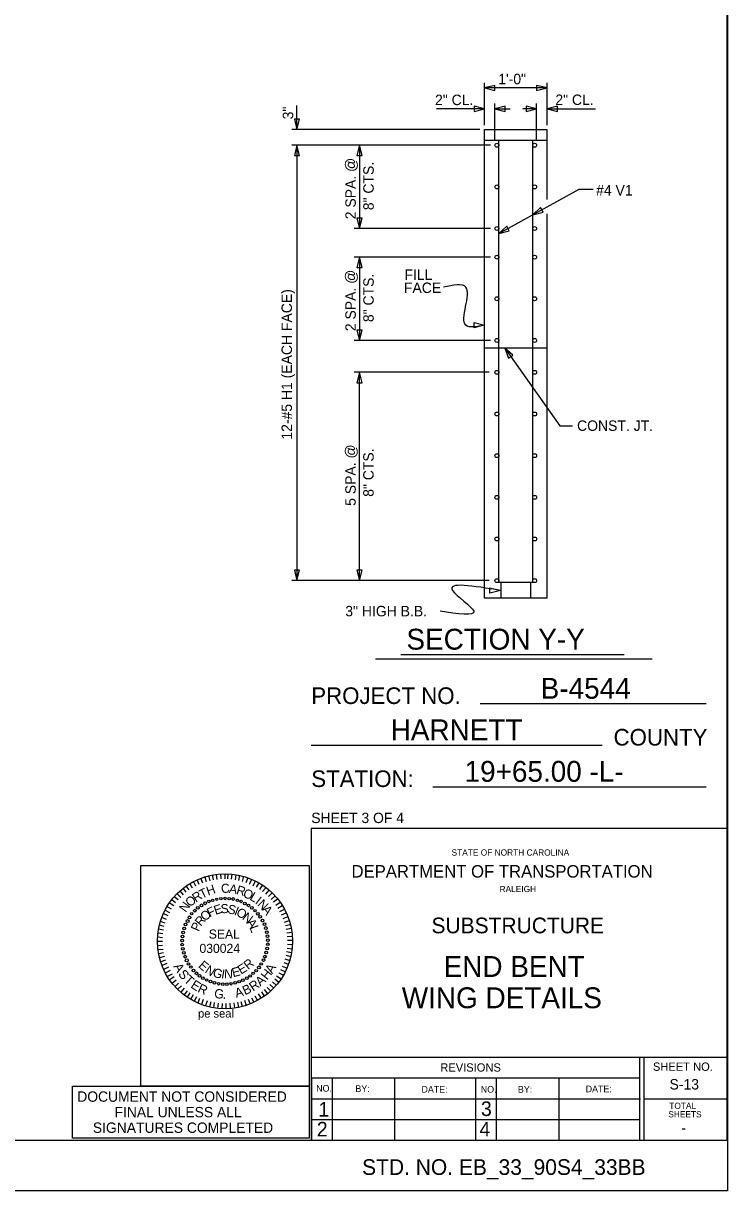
# Model space of a CAD drawing. Extents: x -41 to 251, y -169 to 237.
# Drawn here: x 32.71 to 43.97, y -98.91 to -80.23 of the extents above; entities that cross this region are included whole.
import ezdxf

# ---------------------------------------------------------------- set-up
doc = ezdxf.new("R2010")
doc.units = 0
for name, color, linetype in [('Arrowhead Terminators CELL', 7, 'Continuous'), ('Dimension Lines', 7, 'Continuous'), ('Mis Object Lines', 7, 'Continuous'), ('Mis Object Lines Hidden', 7, 'Continuous'), ('Peseal', 7, 'Continuous'), ('Plan Sheet CELL', 7, 'Continuous'), ('Plot Shape CELL', 7, 'Continuous'), ('Rebar Lines', 7, 'Continuous'), ('Sheet Sticker Exception Certification CELL', 7, 'Continuous'), ('Subtitle Text', 7, 'Continuous'), ('Text', 7, 'Continuous'), ('Title Text', 7, 'Continuous'), ('User Information Notes', 7, 'Continuous'), ('User Information Notes CELL', 7, 'Continuous')]:
    doc.layers.add(name, color=color, linetype=linetype)

msp = doc.modelspace()

# ---------------------------------------------------------------- linework, layer by layer
at = {"layer": 'Arrowhead Terminators CELL'}
for points in [[(40.084, -81.261), (40.25, -81.303), (40.25, -81.22)], [(41.084, -81.261), (40.918, -81.22), (40.918, -81.303)], [(40.084, -81.596), (39.918, -81.554), (39.918, -81.638)], [(40.251, -81.596), (40.417, -81.638), (40.417, -81.554)], [(40.918, -81.595), (40.751, -81.553), (40.751, -81.636)], [(41.084, -81.595), (41.25, -81.636), (41.25, -81.553)], [(37.084, -81.928), (37.126, -81.762), (37.043, -81.762)], [(37.084, -82.178), (37.043, -82.344), (37.126, -82.344)], [(38.084, -82.178), (38.043, -82.344), (38.126, -82.344)], [(40.855, -83.293), (41.021, -83.249), (40.981, -83.176)], [(38.084, -83.511), (38.126, -83.345), (38.043, -83.345)], [(40.314, -83.591), (40.479, -83.547), (40.439, -83.474)], [(38.084, -83.97), (38.043, -84.136), (38.126, -84.136)], [(38.084, -85.303), (38.126, -85.137), (38.043, -85.137)], [(40.084, -85.06), (39.918, -85.101), (39.918, -85.018)], [(40.408, -85.428), (40.47, -85.588), (40.538, -85.539)], [(38.084, -85.813), (38.043, -85.979), (38.126, -85.979)], [(37.084, -89.147), (37.126, -88.98), (37.043, -88.98)], [(38.084, -89.147), (38.126, -88.98), (38.043, -88.98)], [(40.338, -89.304), (40.172, -89.346), (40.172, -89.263)]]:
    msp.add_lwpolyline(points, close=True, dxfattribs=at)
at = {"layer": 'Dimension Lines'}
for p, q in [((40.084, -81.856), (40.084, -81.178)), ((41.084, -81.261), (40.084, -81.261)), ((41.084, -81.856), (41.084, -81.178)), ((37.084, -81.928), (37.084, -81.541)), ((40.084, -81.596), (39.314, -81.596)), ((40.251, -82.106), (40.251, -81.513)), ((40.251, -81.596), (40.497, -81.596)), ((40.918, -81.595), (40.695, -81.595)), ((40.918, -82.106), (40.918, -81.511)), ((41.084, -81.595), (41.859, -81.595)), ((40.012, -81.928), (37.001, -81.928)), ((40.18, -82.178), (37.001, -82.178)), ((37.084, -82.178), (37.084, -89.147)), ((38.084, -82.178), (38.084, -83.511)), ((40.314, -83.591), (41.598, -82.884)), ((41.598, -82.884), (41.824, -82.884)), ((40.18, -83.511), (38.001, -83.511)), ((40.18, -83.97), (38.001, -83.97)), ((38.084, -83.97), (38.084, -85.303)), ((40.18, -85.303), (38.001, -85.303)), ((40.408, -85.428), (41.29, -86.668)), ((40.16, -85.813), (38.001, -85.813)), ((38.084, -89.147), (38.084, -85.813)), ((41.29, -86.668), (41.494, -86.668)), ((40.16, -89.147), (37.001, -89.147))]:
    msp.add_line(p, q, dxfattribs=at)
for points in [[(40.084, -85.06), (39.787, -85.06), (39.787, -84.45), (39.429, -84.45)], [(40.338, -89.304), (39.572, -89.304), (39.911, -89.636), (39.374, -89.636)]]:
    msp.add_spline(points, degree=3, dxfattribs=at)
at = {"layer": 'Mis Object Lines'}
for p, q in [((40.084, -89.428), (40.084, -81.928)), ((40.084, -81.928), (41.084, -81.928)), ((41.084, -83.049), (41.084, -81.928)), ((41.084, -89.428), (41.084, -83.275)), ((41.084, -89.428), (40.084, -89.428))]:
    msp.add_line(p, q, dxfattribs=at)
at = {"layer": 'Mis Object Lines Hidden'}
msp.add_line((41.084, -85.428), (40.084, -85.428), dxfattribs=at)
at = {"layer": 'Peseal'}
for p, q in [((35.465, -94.035), (35.429, -93.962)), ((35.517, -94.009), (35.486, -93.936)), ((35.579, -93.988), (35.548, -93.91)), ((35.637, -93.967), (35.611, -93.884)), ((35.694, -93.952), (35.673, -93.868)), ((35.751, -93.936), (35.735, -93.853)), ((35.808, -93.931), (35.798, -93.848)), ((35.87, -93.92), (35.865, -93.837)), ((35.933, -93.92), (35.933, -93.837)), ((35.979, -93.92), (35.985, -93.837)), ((36.037, -93.926), (36.047, -93.842)), ((36.099, -93.936), (36.109, -93.853)), ((36.156, -93.946), (36.172, -93.863)), ((36.213, -93.962), (36.234, -93.879)), ((36.27, -93.977), (36.302, -93.9)), ((36.327, -94.003), (36.364, -93.926)), ((36.385, -94.029), (36.421, -93.952)), ((35.226, -94.216), (35.164, -94.154)), ((35.268, -94.175), (35.216, -94.113)), ((35.314, -94.133), (35.262, -94.071)), ((35.361, -94.097), (35.314, -94.029)), ((35.413, -94.066), (35.372, -93.993)), ((36.437, -94.055), (36.478, -93.983)), ((36.489, -94.092), (36.535, -94.019)), ((36.535, -94.123), (36.587, -94.061)), ((36.587, -94.165), (36.639, -94.102)), ((36.629, -94.201), (36.686, -94.144)), ((35.112, -94.352), (35.039, -94.305)), ((35.143, -94.305), (35.081, -94.258)), ((35.185, -94.258), (35.122, -94.206)), ((36.67, -94.248), (36.733, -94.19)), ((36.707, -94.289), (36.774, -94.237)), ((36.748, -94.341), (36.816, -94.294)), ((35.023, -94.513), (34.946, -94.476)), ((35.049, -94.461), (34.972, -94.419)), ((35.075, -94.404), (35.003, -94.362)), ((36.779, -94.388), (36.847, -94.346)), ((36.811, -94.44), (36.883, -94.404)), ((36.837, -94.497), (36.909, -94.461)), ((36.863, -94.554), (36.941, -94.523)), ((34.961, -94.684), (34.883, -94.663)), ((34.977, -94.627), (34.899, -94.601)), ((34.997, -94.57), (34.92, -94.539)), ((36.883, -94.611), (36.961, -94.585)), ((36.899, -94.668), (36.977, -94.648)), ((36.909, -94.726), (36.992, -94.71)), ((34.935, -94.861), (34.852, -94.855)), ((34.94, -94.798), (34.862, -94.788)), ((34.951, -94.741), (34.868, -94.726)), ((36.92, -94.783), (37.003, -94.772)), ((36.925, -94.84), (37.008, -94.835)), ((36.93, -94.902), (37.013, -94.902)), ((34.935, -94.923), (34.852, -94.923)), ((34.935, -94.985), (34.852, -94.991)), ((34.946, -95.048), (34.862, -95.058)), ((36.915, -95.084), (36.998, -95.1)), ((36.925, -95.027), (37.008, -95.037)), ((36.93, -94.965), (37.013, -94.97)), ((34.951, -95.105), (34.873, -95.12)), ((34.966, -95.162), (34.883, -95.183)), ((34.982, -95.219), (34.904, -95.245)), ((35.003, -95.276), (34.925, -95.307)), ((36.873, -95.256), (36.951, -95.287)), ((36.889, -95.198), (36.972, -95.224)), ((36.904, -95.141), (36.987, -95.162)), ((35.029, -95.333), (34.951, -95.37)), ((35.055, -95.385), (34.977, -95.427)), ((35.086, -95.443), (35.013, -95.484)), ((36.795, -95.422), (36.868, -95.463)), ((36.821, -95.37), (36.899, -95.406)), ((36.847, -95.318), (36.925, -95.349)), ((35.117, -95.489), (35.049, -95.536)), ((35.153, -95.541), (35.086, -95.593)), ((35.19, -95.588), (35.133, -95.64)), ((35.236, -95.63), (35.174, -95.692)), ((36.65, -95.609), (36.712, -95.671)), ((36.691, -95.567), (36.754, -95.624)), ((36.728, -95.521), (36.795, -95.572)), ((36.759, -95.474), (36.831, -95.521)), ((35.278, -95.671), (35.226, -95.734)), ((35.325, -95.713), (35.278, -95.775)), ((35.372, -95.744), (35.325, -95.811)), ((35.424, -95.775), (35.382, -95.848)), ((35.475, -95.806), (35.439, -95.879)), ((35.527, -95.832), (35.496, -95.905)), ((36.359, -95.822), (36.395, -95.895)), ((36.411, -95.791), (36.452, -95.869)), ((36.463, -95.759), (36.509, -95.832)), ((36.515, -95.728), (36.561, -95.796)), ((36.561, -95.692), (36.613, -95.759)), ((36.608, -95.656), (36.66, -95.713)), ((35.585, -95.853), (35.559, -95.931)), ((35.647, -95.874), (35.621, -95.952)), ((35.704, -95.889), (35.683, -95.967)), ((35.761, -95.9), (35.746, -95.983)), ((35.824, -95.91), (35.813, -95.993)), ((35.886, -95.915), (35.881, -95.998)), ((35.948, -95.915), (35.948, -95.998)), ((36.011, -95.91), (36.016, -95.993)), ((36.073, -95.905), (36.083, -95.988)), ((36.13, -95.895), (36.146, -95.978)), ((36.187, -95.884), (36.208, -95.962)), ((36.244, -95.863), (36.27, -95.947)), ((36.302, -95.843), (36.333, -95.921))]:
    msp.add_line(p, q, dxfattribs=at)
for centre, radius in [((35.556, -94.344), 0.0223), ((35.616, -94.31), 0.0232), ((35.675, -94.281), 0.0198), ((35.735, -94.261), 0.0189), ((35.8, -94.245), 0.0184), ((35.868, -94.237), 0.0209), ((35.933, -94.232), 0.0208), ((35.998, -94.237), 0.0209), ((36.063, -94.242), 0.0214), ((36.13, -94.261), 0.0189), ((36.19, -94.281), 0.0198), ((36.25, -94.313), 0.0209), ((36.307, -94.344), 0.0209), ((35.364, -94.536), 0.0223), ((35.4, -94.479), 0.0184), ((35.449, -94.429), 0.022), ((35.499, -94.385), 0.0223), ((36.361, -94.383), 0.0203), ((36.413, -94.429), 0.0203), ((36.457, -94.479), 0.0203), ((36.496, -94.528), 0.0209), ((35.278, -94.713), 0.0222), ((35.301, -94.65), 0.0198), ((35.333, -94.596), 0.0239), ((36.533, -94.585), 0.0209), ((36.564, -94.645), 0.0198), ((36.587, -94.707), 0.0222), ((35.247, -94.907), 0.0208), ((35.252, -94.843), 0.0209), ((35.262, -94.778), 0.0214), ((36.603, -94.772), 0.0214), ((36.613, -94.837), 0.0209), ((36.618, -94.902), 0.0208), ((35.247, -94.972), 0.0209), ((35.257, -95.04), 0.0209), ((35.273, -95.105), 0.0214), ((36.592, -95.1), 0.0214), ((36.608, -95.035), 0.0209), ((36.618, -94.967), 0.0209), ((35.294, -95.165), 0.0222), ((35.32, -95.224), 0.0232), ((35.348, -95.282), 0.0209), ((36.512, -95.282), 0.0209), ((36.548, -95.219), 0.0209), ((36.572, -95.165), 0.0222), ((35.387, -95.331), 0.0203), ((35.429, -95.385), 0.022), ((35.475, -95.432), 0.022), ((35.525, -95.471), 0.0223), ((36.335, -95.474), 0.0203), ((36.382, -95.432), 0.0203), ((36.431, -95.388), 0.0203), ((36.476, -95.336), 0.0223), ((35.579, -95.508), 0.0209), ((35.639, -95.539), 0.0198), ((35.701, -95.562), 0.0222), ((35.766, -95.583), 0.0214), ((35.831, -95.598), 0.0209), ((35.896, -95.604), 0.0208), ((35.964, -95.604), 0.0208), ((36.029, -95.598), 0.0209), ((36.094, -95.583), 0.0214), ((36.159, -95.565), 0.0198), ((36.218, -95.541), 0.0232), ((36.281, -95.508), 0.0209)]:
    msp.add_circle(centre, radius, dxfattribs=at)
at = {"layer": 'Plan Sheet CELL'}
for p, q in [((43.962, -70.174), (43.962, -98.104)), ((43.63, -91.121), (40.016, -91.121)), ((41.967, -91.786), (37.313, -91.786)), ((43.63, -92.45), (39.255, -92.45)), ((43.962, -93.116), (37.313, -93.116)), ((37.313, -93.116), (37.313, -98.104)), ((37.313, -96.773), (43.962, -96.773)), ((42.566, -96.773), (42.566, -98.104)), ((42.633, -96.773), (42.633, -98.104)), ((37.313, -97.105), (42.569, -97.105)), ((37.317, -97.105), (37.317, -98.104)), ((37.645, -97.105), (37.645, -98.104)), ((38.642, -97.111), (38.642, -98.109)), ((39.94, -97.105), (39.94, -98.112)), ((40.273, -97.105), (40.273, -98.104)), ((41.271, -97.105), (41.271, -98.104)), ((37.313, -97.438), (42.58, -97.438)), ((42.633, -97.438), (43.951, -97.438)), ((37.313, -97.771), (42.569, -97.771)), ((1.402, -98.104), (43.962, -98.104)), ((43.974, -98.91), (43.974, -98.91))]:
    msp.add_line(p, q, dxfattribs=at)
at = {"layer": 'Plot Shape CELL'}
msp.add_lwpolyline([(0, -69.65), (43.974, -69.65), (43.974, -98.91), (0, -98.91)], close=True, dxfattribs=at)
at = {"layer": 'Rebar Lines'}
for p, q in [((40.314, -89.178), (40.314, -82.095)), ((40.855, -89.178), (40.855, -82.095)), ((40.886, -89.178), (40.282, -89.178)), ((40.346, -89.178), (40.346, -89.428)), ((40.821, -89.178), (40.821, -89.428))]:
    msp.add_line(p, q, dxfattribs=at)
for centre in [(40.282, -82.178), (40.886, -82.178), (40.282, -82.845), (40.886, -82.845), (40.282, -83.511), (40.886, -83.511), (40.282, -83.97), (40.886, -83.97), (40.282, -84.636), (40.886, -84.636), (40.282, -85.303), (40.886, -85.303), (40.282, -85.813), (40.886, -85.813), (40.282, -86.48), (40.886, -86.48), (40.282, -87.147), (40.886, -87.147), (40.282, -87.813), (40.886, -87.813), (40.282, -88.48), (40.886, -88.48), (40.282, -89.147), (40.886, -89.147)]:
    msp.add_ellipse(centre, major_axis=(0, -0.0313), ratio=0.99999, dxfattribs=at)
at = {"layer": 'Sheet Sticker Exception Certification CELL'}
msp.add_lwpolyline([(33.491, -97.237), (37.279, -97.237), (37.279, -98.07), (33.491, -98.07)], close=True, dxfattribs=at)
at = {"layer": 'Title Text'}
for p, q in [((38.342, -90.4), (42.764, -90.4)), ((38.745, -90.327), (42.319, -90.327))]:
    msp.add_line(p, q, dxfattribs=at)
at = {"layer": 'User Information Notes'}
msp.add_line((35.933, -94.918), (35.933, -94.918), dxfattribs=at)
at = {"layer": 'User Information Notes CELL'}
for p, q in [((40.084, -82.095), (41.084, -82.095)), ((35.933, -94.918), (35.933, -94.918))]:
    msp.add_line(p, q, dxfattribs=at)
msp.add_lwpolyline([(34.586, -93.704), (37.279, -93.704), (37.279, -97.237), (34.586, -97.237)], close=True, dxfattribs=at)
msp.add_circle((35.933, -94.918), 1.081, dxfattribs=at)

# ---------------------------------------------------------------- texts
at = {"layer": 'Peseal'}
for s, height, rotation, p in [('R', 0.145, 32.9699, (35.465, -94.3)), ('T', 0.145, 25.943, (35.564, -94.242)), ('H', 0.145, 18.9162, (35.662, -94.19)), ('C', 0.145, 4.8625, (35.875, -94.149)), ('A', 0.145, 350.8088, (35.99, -94.144)), ('R', 0.145, 343.7819, (36.104, -94.159)), ('O', 0.145, 336.7551, (36.208, -94.201)), ('L', 0.145, 329.7282, (36.317, -94.248)), ('N', 0.145, 54.0504, (35.304, -94.466)), ('O', 0.145, 39.9967, (35.372, -94.378)), ('E', 0.145, 18.4448, (35.782, -94.497)), ('S', 0.145, 2.3789, (35.865, -94.471)), ('S', 0.145, 346.313, (35.964, -94.466)), ('I', 0.145, 322.7014, (36.405, -94.305)), ('N', 0.145, 315.6745, (36.442, -94.336)), ('R', 0.145, 50.5765, (35.548, -94.689)), ('O', 0.145, 42.5436, (35.616, -94.606)), ('F', 0.145, 26.4777, (35.688, -94.539)), ('I', 0.145, 338.28, (36.068, -94.492)), ('O', 0.145, 330.2471, (36.099, -94.497)), ('N', 0.145, 322.2141, (36.198, -94.559)), ('A', 0.145, 308.6477, (36.515, -94.414)), ('P', 0.145, 66.6424, (35.512, -94.772)), ('A', 0.145, 306.1483, (36.27, -94.622)), ('L', 0.145, 290.0824, (36.322, -94.694)), ('E', 0.145, 318.5179, (35.496, -95.323)), ('E', 0.145, 30.6815, (36.187, -95.453)), ('R', 0.145, 38.6997, (36.302, -95.38)), ('A', 0.148, 300.3993, (35.102, -95.321)), ('S', 0.148, 309.4349, (35.175, -95.447)), ('T', 0.148, 318.1096, (35.264, -95.555)), ('N', 0.145, 326.5361, (35.6, -95.411)), ('G', 0.145, 342.5725, (35.725, -95.479)), ('I', 0.145, 350.5906, (35.865, -95.51)), ('N', 0.145, 358.6088, (35.917, -95.51)), ('E', 0.145, 14.6452, (36.063, -95.495)), ('H', 0.148, 51.3597, (36.606, -95.549)), ('A', 0.148, 59.6007, (36.69, -95.446)), ('E', 0.148, 327.1453, (35.372, -95.652)), ('R', 0.148, 335.458, (35.484, -95.725)), ('B', 0.148, 24.8312, (36.253, -95.784)), ('R', 0.148, 33.5776, (36.381, -95.725)), ('A', 0.148, 42.3241, (36.499, -95.647)), ('G', 0.148, 353.3858, (35.754, -95.824)), ('.', 0.148, 2.1323, (35.894, -95.841)), ('A', 0.148, 15.7955, (36.113, -95.824))]:
    msp.add_text(s, height=height, rotation=rotation, dxfattribs=at).set_placement(p)
for s, p in [('SEAL', (35.673, -94.876)), ('030024', (35.524, -95.105))]:
    msp.add_text(s, height=0.1455, dxfattribs=at).set_placement(p)
at = {"layer": 'Plan Sheet CELL'}
for s, height, p in [('PROJECT NO.', 0.266, (37.313, -91.121)), ('COUNTY', 0.266, (42.149, -91.786)), ('STATION:', 0.266, (37.313, -92.45)), ('SHEET 3 OF 4', 0.16625, (37.313, -93.027)), ('STATE OF NORTH CAROLINA', 0.09974, (39.557, -93.548)), ('DEPARTMENT OF TRANSPORTATION', 0.19949, (37.957, -93.899)), ('RALEIGH', 0.0997, (40.325, -94.132)), ('REVISIONS', 0.133, (39.377, -97.005)), ('SHEET NO.', 0.133, (42.779, -96.992)), ('NO.', 0.106, (37.391, -97.325)), ('BY:', 0.106, (38.019, -97.33)), ('DATE:', 0.106, (39.076, -97.341)), ('NO.', 0.106, (40.025, -97.341)), ('BY:', 0.106, (40.619, -97.342)), ('DATE:', 0.106, (41.703, -97.335)), ('1', 0.233, (37.426, -97.726)), ('3', 0.233, (40.027, -97.715)), ('TOTAL', 0.0997, (43.04, -97.602)), ('SHEETS', 0.0997, (43.024, -97.737)), ('2', 0.233, (37.402, -98.042)), ('4', 0.233, (40.003, -98.042))]:
    msp.add_text(s, height=height, dxfattribs=at).set_placement(p)
at = {"layer": 'Sheet Sticker Exception Certification CELL'}
for s, p in [('DOCUMENT NOT CONSIDERED', (33.569, -97.487)), ('FINAL UNLESS ALL', (34.165, -97.736)), ('SIGNATURES COMPLETED', (33.819, -97.985))]:
    msp.add_text(s, height=0.16588, dxfattribs=at).set_placement(p)
at = {"layer": 'Subtitle Text'}
for s, p in [('SUBSTRUCTURE', (39.236, -94.791)), ('STD. NO. EB_33_90S4_33BB', (38.126, -98.658))]:
    msp.add_text(s, height=0.25108, dxfattribs=at).set_placement(p)
at = {"layer": 'Text'}
for s, rotation, p in [('1\'-0"', 360, (40.304, -81.202)), ('2" CL.', 360, (39.293, -81.536)), ('2" CL.', 360, (41.218, -81.534)), ('3"', 90, (37.024, -81.764)), ('2 SPA. @', 90, (38.025, -83.363)), ('8" CTS.', 90, (38.312, -83.218)), ('#4 V1', 360, (41.87, -82.983)), ('2 SPA. @', 90, (38.025, -85.154)), ('8" CTS.', 90, (38.312, -85.009)), ('FILL', 360, (38.803, -84.334)), ('FACE', 360, (38.795, -84.543)), ('12-#5 H1 (EACH FACE)', 90, (37.004, -86.89)), ('CONST. JT.', 360, (41.565, -86.75)), ('5 SPA. @', 90, (38.024, -87.95)), ('8" CTS.', 90, (38.311, -87.805))]:
    msp.add_text(s, height=0.167, rotation=rotation, dxfattribs=at).set_placement(p)
for s, p in [('3" HIGH B.B.', (37.857, -89.718)), ('S-13', (43.044, -97.291)), ('-', (43.232, -97.987))]:
    msp.add_text(s, height=0.167, dxfattribs=at).set_placement(p)
at = {"layer": 'Title Text'}
for s, height, p in [('SECTION Y-Y', 0.33399, (38.835, -90.251)), ('B-4544', 0.334, (40.983, -91.037)), ('HARNETT', 0.334, (38.583, -91.702)), ('19+65.00 -L-', 0.334, (39.765, -92.366)), ('END BENT', 0.334, (39.43, -95.489)), ('WING DETAILS', 0.33399, (38.761, -95.99))]:
    msp.add_text(s, height=height, dxfattribs=at).set_placement(p)
at = {"layer": 'User Information Notes CELL'}
msp.add_text('pe seal', height=0.133, dxfattribs=at).set_placement((35.502, -96.14))

doc.saveas('drawing.dxf')
